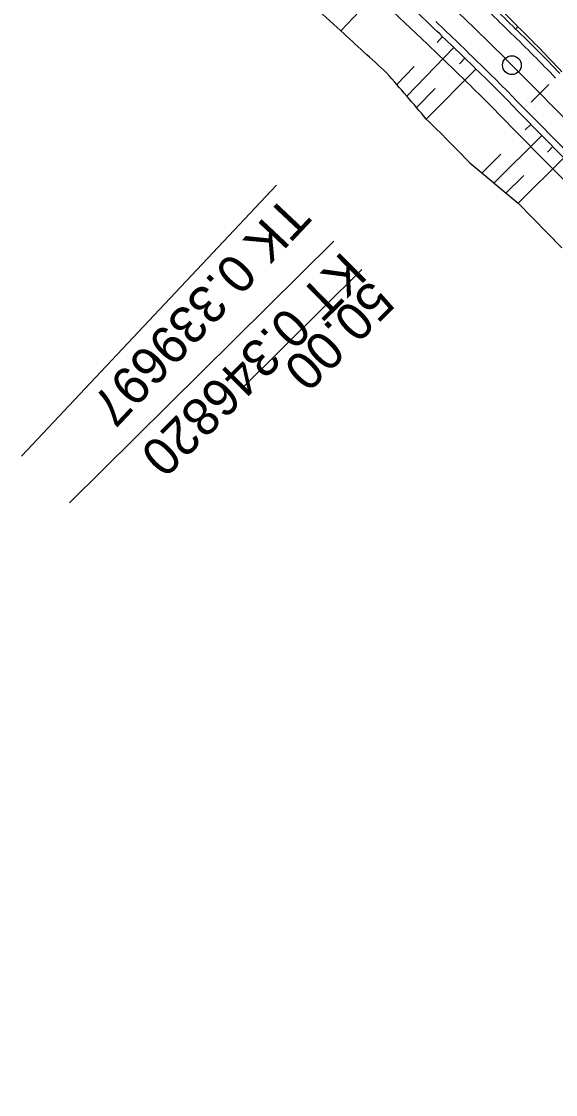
# Model space of a CAD drawing. Extents: x -481645 to -478728, y -1113199 to -1110710.
# Drawn here: x -481511.9 to -481469.2, y -1112911.3 to -1112825.6 of the extents above; entities that cross this region are included whole.
import ezdxf

# ---------------------------------------------------------------- set-up
doc = ezdxf.new("R2010")
doc.units = 0
for name, color, linetype in [('Vrstva 41', 7, 'Continuous'), ('Vrstva 42', 7, 'Continuous'), ('Vrstva 43', 7, 'Continuous'), ('Vrstva 44', 7, 'Continuous'), ('Vrstva 45', 7, 'Continuous'), ('Vrstva 46', 7, 'Continuous'), ('Vrstva 47', 7, 'Continuous'), ('Vrstva 48', 7, 'Continuous'), ('Vrstva 50', 7, 'Continuous'), ('Vrstva 51', 7, 'Continuous')]:
    doc.layers.add(name, color=color, linetype=linetype)

msp = doc.modelspace()

# ---------------------------------------------------------------- linework, layer by layer
at = {"layer": 'Vrstva 41'}
msp.add_line((-481472.723, -1112829.041), (-481391.265, -1112911.275), dxfattribs=at)
msp.add_arc((-481614.814, -1112969.79), 200, 44.72835, 46.76892, dxfattribs=at)
at = {"layer": 'Vrstva 42'}
for p, q in [((-481490.06, -1112822.927), (-481486.377, -1112826.309)), ((-481476.094, -1112836.855), (-481472.235, -1112840.07)), ((-481472.235, -1112840.07), (-481468.725, -1112843.631))]:
    msp.add_line(p, q, dxfattribs=at)
for centre, radius, start, end in [((-481617.817, -1112966.825), 202.563, 44.05596, 45.48866), ((-481875.338, -1113253.458), 577.708, 47.184261, 47.679069), ((-481543.121, -1112898.281), 101.255, 42.73092, 45.57354), ((-481627.108, -1112956.741), 192.344, 39.90476, 41.3434), ((-481546.131, -1112902.6), 96.06, 43.18967, 46.12949)]:
    msp.add_arc(centre, radius, start, end, dxfattribs=at)
at = {"layer": 'Vrstva 43'}
for p, q in [((-481472.979, -1112833.769), (-481469.456, -1112837.317)), ((-481469.456, -1112837.317), (-481465.933, -1112840.865))]:
    msp.add_line(p, q, dxfattribs=at)
for centre, radius, start, end in [((-481885.088, -1113255.041), 589.438, 46.590286, 47.075792), ((-481614.646, -1112969.951), 196.482, 45.31768, 46.75007), ((-481544.311, -1112901.321), 98.243, 43.4406, 46.33828)]:
    msp.add_arc(centre, radius, start, end, dxfattribs=at)
at = {"layer": 'Vrstva 44'}
msp.add_line((-481472.084, -1112832.883), (-481468.566, -1112836.435), dxfattribs=at)
for centre, radius, start, end in [((-481887.327, -1113256.422), 593.25, 46.525047, 47.007617), ((-481614.814, -1112969.79), 202.25, 45.24988, 46.68226), ((-481614.814, -1112969.79), 197.75, 45.24988, 46.68226), ((-481542.36, -1112899.2), 101.125, 43.40156, 46.24636), ((-481543.948, -1112900.793), 98.875, 43.3797, 46.26551)]:
    msp.add_arc(centre, radius, start, end, dxfattribs=at)
at = {"layer": 'Vrstva 45'}
msp.add_line((-481471.729, -1112832.531), (-481468.21, -1112836.083), dxfattribs=at)
for centre, radius, start, end in [((-481614.814, -1112969.79), 201.75, 45.24988, 46.68226), ((-481614.814, -1112969.79), 198.25, 45.24988, 46.68226), ((-481542.537, -1112899.377), 100.875, 43.39918, 46.24844), ((-481543.772, -1112900.616), 99.125, 43.38217, 46.26333)]:
    msp.add_arc(centre, radius, start, end, dxfattribs=at)
at = {"layer": 'Vrstva 46'}
msp.add_line((-481471.729, -1112832.531), (-481468.21, -1112836.083), dxfattribs=at)
for centre, radius, start, end in [((-481614.814, -1112969.79), 201.75, 45.24988, 46.68226), ((-481614.814, -1112969.79), 198.25, 45.24988, 46.68226), ((-481542.537, -1112899.377), 100.875, 43.39918, 46.24844), ((-481543.772, -1112900.616), 99.125, 43.38217, 46.26333)]:
    msp.add_arc(centre, radius, start, end, dxfattribs=at)
at = {"layer": 'Vrstva 47'}
for p, q in [((-481471.196, -1112832.003), (-481469.775, -1112830.596)), ((-481484.695, -1112845.374), (-481494.286, -1112854.875))]:
    msp.add_line(p, q, dxfattribs=at)
at = {"layer": 'Vrstva 48'}
for p, q in [((-481491.524, -1112838.642), (-481511.867, -1112860.282)), ((-481486.932, -1112843.115), (-481508.033, -1112864.017))]:
    msp.add_line(p, q, dxfattribs=at)
msp.add_circle((-481472.723, -1112829.041), 0.75, dxfattribs=at)
at = {"layer": 'Vrstva 50'}
msp.add_line((-481472.426, -1112826.155), (-481472.243, -1112825.97), dxfattribs=at)
at = {"layer": 'Vrstva 51'}
for p, q in [((-481482.789, -1112822.492), (-481486.377, -1112826.309)), ((-481478.252, -1112826.765), (-481478.69, -1112827.224)), ((-481477.361, -1112827.622), (-481481.118, -1112831.508)), ((-481480.518, -1112829.138), (-481481.907, -1112830.594)), ((-481476.475, -1112828.484), (-481476.918, -1112828.936)), ((-481475.594, -1112829.351), (-481479.558, -1112833.35)), ((-481478.848, -1112830.908), (-481480.335, -1112832.427)), ((-481471.205, -1112833.771), (-481471.652, -1112834.214)), ((-481470.325, -1112834.659), (-481474.164, -1112838.462)), ((-481473.614, -1112836.158), (-481475.129, -1112837.659)), ((-481469.445, -1112835.547), (-481469.891, -1112835.988)), ((-481468.566, -1112836.435), (-481472.235, -1112840.07)), ((-481471.768, -1112837.848), (-481473.199, -1112839.266))]:
    msp.add_line(p, q, dxfattribs=at)

# ---------------------------------------------------------------- texts
at = {"layer": 'Vrstva 47'}
msp.add_text('50.00', height=3, rotation=224.72836, dxfattribs=at).set_placement((-481483.99, -1112846.084))
at = {"layer": 'Vrstva 48'}
for s, height, rotation, p in [('TK 0.339697', 2.999, 226.76893, (-481490.795, -1112839.327)), ('KT 0.346820', 3, 224.72836, (-481486.228, -1112843.825))]:
    msp.add_text(s, height=height, rotation=rotation, dxfattribs=at).set_placement(p)

doc.saveas('drawing.dxf')
